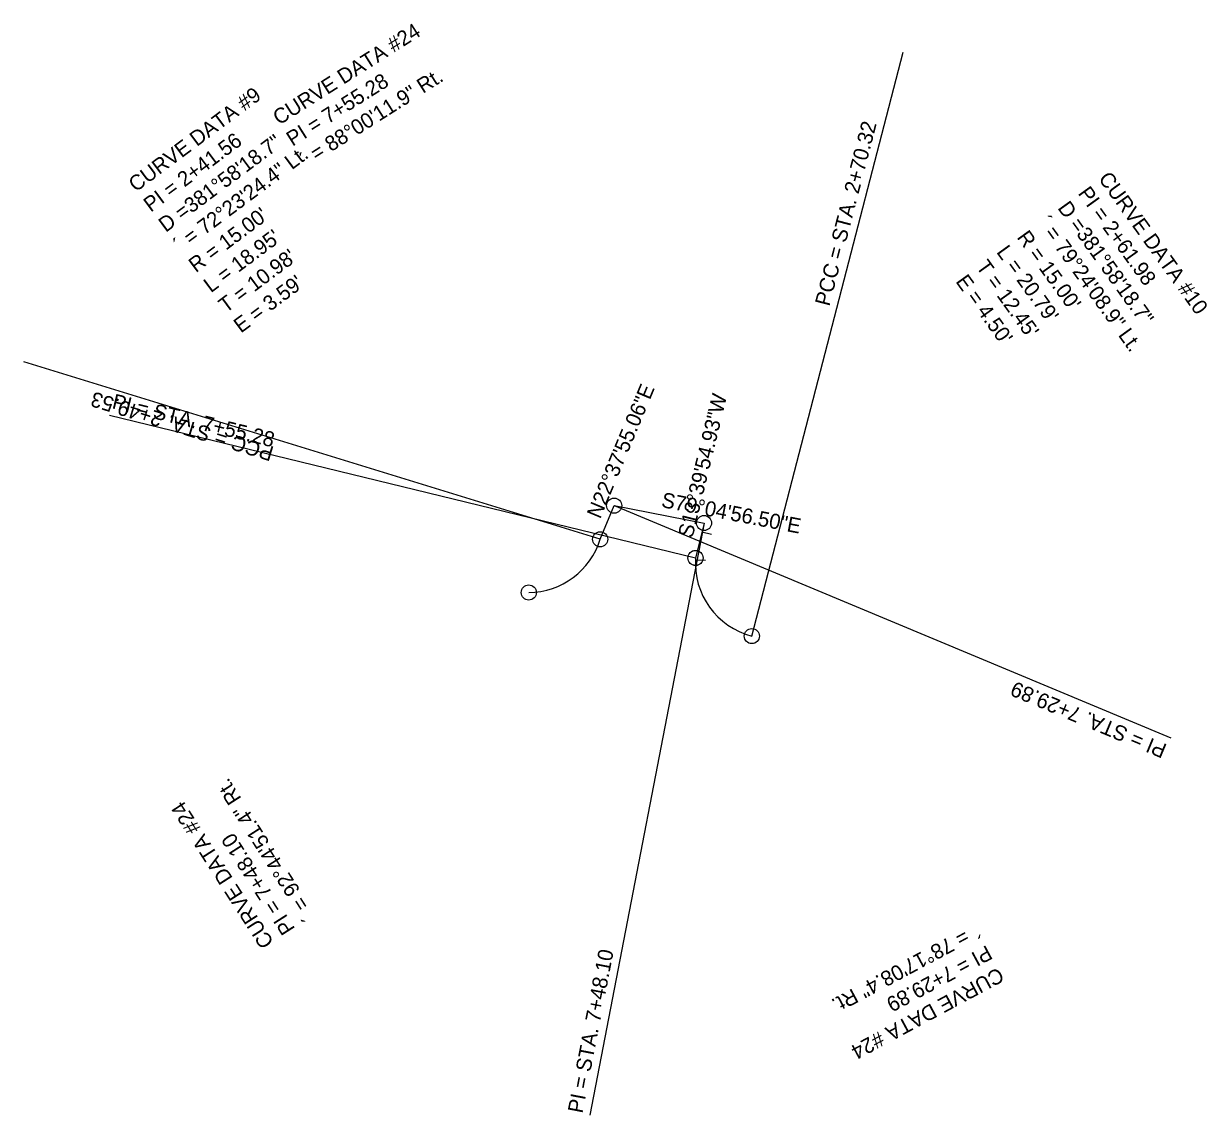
# Model space of a CAD drawing. Extents: x 1158784 to 1165006, y 610007 to 611539.
# Drawn here: x 1163291.5 to 1163527, y 610356.7 to 610573.8 of the extents above; entities that cross this region are included whole.
import ezdxf

# ---------------------------------------------------------------- set-up
doc = ezdxf.new("R2010")
doc.units = 0
for name, color, linetype in [('D_Roadway_Centerline', 7, 'Continuous'), ('D_Roadway_Centerline_Bearings', 7, 'Continuous'), ('D_Roadway_Centerline_CurveData', 7, 'Continuous'), ('D_Roadway_Centerline_Flags', 7, 'Continuous'), ('D_Roadway_Centerline_Text', 7, 'Continuous')]:
    doc.layers.add(name, color=color, linetype=linetype)

msp = doc.modelspace()

# ---------------------------------------------------------------- linework, layer by layer
at = {"layer": 'D_Roadway_Centerline'}
for p, q in [((1163406.16, 610471.27), (1163408.95, 610477.96)), ((1163408.95, 610477.96), (1163426.83, 610474.51)), ((1163426.83, 610474.51), (1163425.14, 610467.54))]:
    msp.add_line(p, q, dxfattribs=at)
for centre, start, end in [((1163391.83, 610475.68), 270.5073, 342.8974), ((1163440.1, 610466.54), 176.0725, 255.475)]:
    msp.add_arc(centre, 15, start, end, dxfattribs=at)
at = {"layer": 'D_Roadway_Centerline_Flags'}
for points in [[(1163436.34, 610452.02), (1163466.44, 610568.18)], [(1163406.16, 610471.27), (1163291.47, 610506.56)], [(1163425.14, 610467.54), (1163308.53, 610495.89)], [(1163408.95, 610477.96), (1163519.71, 610431.79)], [(1163426.83, 610474.51), (1163404.1, 610356.69)]]:
    msp.add_lwpolyline(points, dxfattribs=at)
for centre in [(1163408.95, 610477.96), (1163426.83, 610474.51), (1163406.16, 610471.27), (1163406.16, 610471.27), (1163425.14, 610467.56), (1163425.14, 610467.54), (1163391.96, 610460.68), (1163436.34, 610452.02)]:
    msp.add_circle(centre, 1.5, dxfattribs=at)
at = {"layer": 'D_Roadway_Centerline_Text'}
for points in [[(1163428.33, 610472.2), (1163426.38, 610472.67)], [(1163427.11, 610467.02), (1163425.11, 610467.09)]]:
    msp.add_lwpolyline(points, dxfattribs=at)

# ---------------------------------------------------------------- texts
at = {"layer": 'D_Roadway_Centerline_Bearings'}
for s, rotation, p in [('N22%%d37\'55.06"E', 67.368, (1163406.17, 610475.19)), ('S13%%d39\'54.93"W', 76.3347, (1163424.53, 610471.38)), ('S79%%d04\'56.50"E', 349.0824, (1163418.18, 610477.71))]:
    msp.add_text(s, height=3, rotation=rotation, dxfattribs=at).set_placement(p)
at = {"layer": 'D_Roadway_Centerline_CurveData'}
for s, rotation, p in [('CURVE DATA #24', 32.3331, (1163342.28, 610553.57)), ('PI = 7+55.28', 32.3331, (1163344.96, 610549.34)), ('´ = 88%%d00\'11.9" Rt.', 32.3331, (1163347.63, 610545.12)), ('CURVE DATA #9', 36.7024, (1163313.77, 610540.24)), ('PI = 2+41.56', 36.7024, (1163316.75, 610536.23)), ('D =381%%d58\'18.7"', 36.7024, (1163319.74, 610532.22)), ('´ = 72%%d23\'24.4" Lt.', 36.7024, (1163322.73, 610528.21)), ('CURVE DATA #10', 305.7737, (1163505.18, 610543.01)), ('PI = 2+61.98', 305.7737, (1163501.12, 610540.08)), ("R = 15.00'", 36.7024, (1163325.72, 610524.2)), ('D =381%%d58\'18.7"', 305.7737, (1163497.07, 610537.16)), ('´ = 79%%d24\'08.9" Lt.', 305.7737, (1163493.01, 610534.24)), ("L = 18.95'", 36.7024, (1163328.71, 610520.19)), ("R = 15.00'", 305.7737, (1163488.95, 610531.32)), ("L = 20.79'", 305.7737, (1163484.9, 610528.39)), ("T = 10.98'", 36.7024, (1163331.7, 610516.18)), ("T = 12.45'", 305.7737, (1163480.84, 610525.47)), ("E = 3.59'", 36.7024, (1163334.68, 610512.18)), ("E = 4.50'", 305.7737, (1163476.78, 610522.55)), ('´ = 92%%d44\'51.4" Rt.', 122.7086, (1163349.77, 610396.5)), ('CURVE DATA #24', 122.7086, (1163341.35, 610391.1)), ('PI = 7+48.10', 122.7086, (1163345.56, 610393.8)), ('´ = 78%%d17\'08.4" Rt.', 208.2252, (1163480.7, 610395.04)), ('PI = 7+29.89', 208.2252, (1163483.07, 610390.63)), ('CURVE DATA #24', 208.2252, (1163485.43, 610386.23))]:
    msp.add_text(s, height=3, rotation=rotation, dxfattribs=at).set_placement(p)
at = {"layer": 'D_Roadway_Centerline_Flags'}
for s, rotation, p in [('PCC = STA. 2+70.32', 75.475, (1163451.76, 610517.49)), ('PCC = STA. 2+49.53', 162.8974, (1163341.45, 610489.61)), ('PI = STA. 7+55.28', 346.3347, (1163308.89, 610497.35)), ('PI = STA. 7+29.89', 157.368, (1163519.14, 610430.4)), ('PI = STA. 7+48.10', 79.0824, (1163402.63, 610356.97))]:
    msp.add_text(s, height=3, rotation=rotation, dxfattribs=at).set_placement(p)

doc.saveas('drawing.dxf')
